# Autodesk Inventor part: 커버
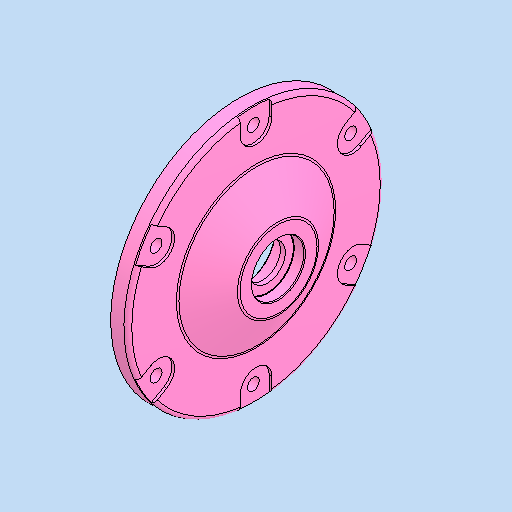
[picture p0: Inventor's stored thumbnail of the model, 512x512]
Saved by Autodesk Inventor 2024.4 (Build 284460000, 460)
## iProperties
Created: 2025-11
Part Number: 커버
Material: 알루미늄 6061
Document SubType Name: Modeling
Designer: home
Density: 2.7 g/cm^3
Appearance: 기본값
Author: jhkim
Sending System: Autodesk Inventor 2026
Preprocessor: ST-DEVELOPER v20.1
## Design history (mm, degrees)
feature "솔리드1"
node "솔리드2"
